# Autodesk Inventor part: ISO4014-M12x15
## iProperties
Created: 2001-12
Part Number: ISO4014-M12x15
Document SubType Name: Modeling
Designer: Tobben
Control State: 0
Master: False
Checked Out: False
Shininess: 64.0
Length Units: 11269
Angle Units: 11279
Time Units: 11290
Mass Units: 11283
Length Display Precision: 3
Angle Display Precision: 2
Density: 0.0
Volumn: 0.0
Area: 0.0
PropertySet Name: Model Information
Author: Tobben
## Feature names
1. Base1
